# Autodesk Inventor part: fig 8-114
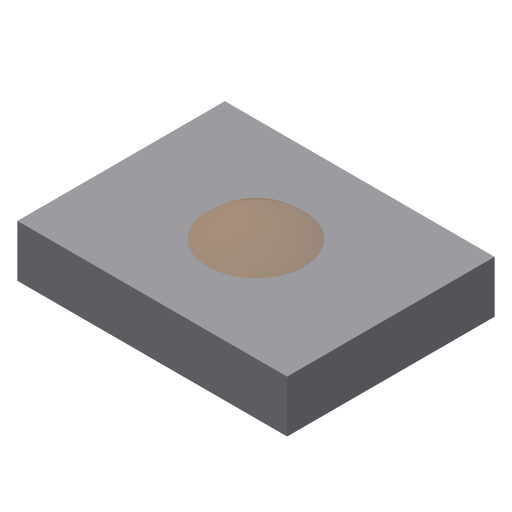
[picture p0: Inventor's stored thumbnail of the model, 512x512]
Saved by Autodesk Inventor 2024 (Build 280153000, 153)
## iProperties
Created: 2009-09
Part Number: fig 8-114
Document SubType Name: Modeling
Designer: Sham
Density: 1 g/cm^3
Material: Generic
Appearance: Default
Author: Sham
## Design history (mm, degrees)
sketch "Sketch1"
  geometry: L1 (-26, 20)-(0, 20); L2 (0, 20)-(0, 0); L3 (0, 0)-(-26, 0); L4 (-26, 0)-(-26, 20)
  constraints: 8 end point, 2 parallel, 1 horizontal, 1 perpendicular
extrude "Extrusion1" new body sketch "Sketch1" distance "d0" = 5; taper "d1" = 0 deg
workplane "Work Plane1"
sketch "Sketch2"
  geometry: L1 (13, 8)-(13, 5); A1 r 7.517 centre (12.377, -0.349) between (17.658, 5) and (13, 7.142)
  constraints: 2 end point, 2 point on circle, 1 centre point
feature "RevolutionSrf2" sketch "Sketch2" dims angle "d4" = 90 deg
body "Solid1"
body "Srf2"
